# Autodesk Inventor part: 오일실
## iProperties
Created: 2009-02
Part Number: 오일실
Material: 고무
Description: 오일-실
Document SubType Name: Modeling
Standard: KS B 2804
Designer: 한국산업디자인학원-SeoGD™
Standards Organization: KS
Language: ko-KR
Size Designation: S - 12 22 7
Categories: <MemberInstance><Categories><Category DisplayName="샤프트 부품" InternalName="7f7aeb1f-a693-4053-b835-cee3144e0d98" Mnemonic="SHFT"><Category DisplayName="실링" Intern
Density: 0.93 g/cm^3
IsCustomPart: 1
Author: 진현석
